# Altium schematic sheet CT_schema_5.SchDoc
size 300 x 247 mm
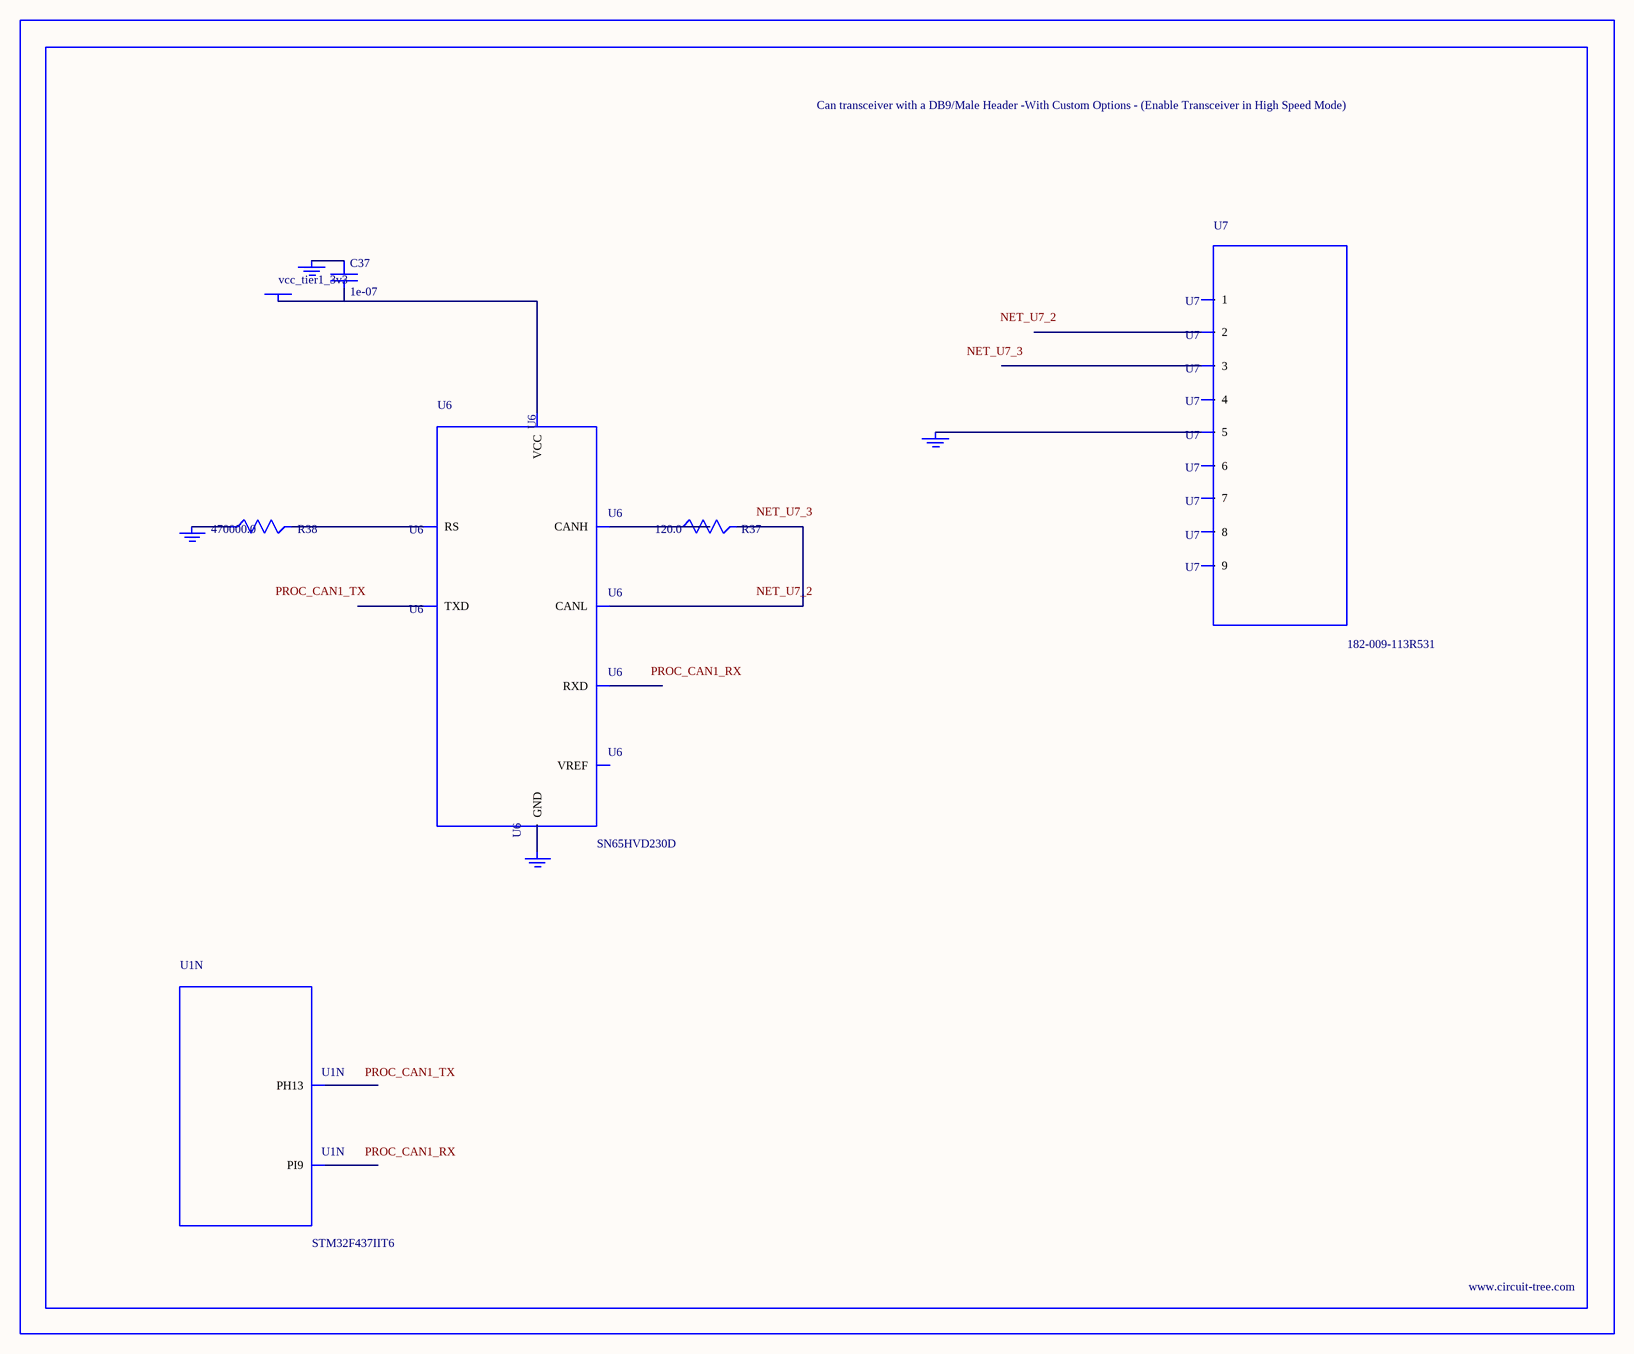
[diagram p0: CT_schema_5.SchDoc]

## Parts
BORDER4  (no value)
C37  1e-07  [C0402]
GND_INSTANCE_4_0  (no value)
GND_INSTANCE_4_1  (no value)
GND_INSTANCE_4_2  (no value)
GND_INSTANCE_4_3  (no value)
POWER_INSTANCE_4_0  vcc_tier1_3v3
R37  120.0  [R0603]
R38  470000.0  [R0603]
U1  STM32F437IIT6  [LQFP176]  (part N of 16)
U6  SN65HVD230D  [SOIC-8]
U7  182-009-113R531  [182-009-MALE]

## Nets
NetC37_1: C37.1 GND_INSTANCE_4_0.0(GND)
NetC37_2: C37.2 POWER_INSTANCE_4_0.0(PWR) U6.3(VCC)
NetGND_INSTANCE_4_1_0: GND_INSTANCE_4_1.0(GND) R38.1
NetGND_INSTANCE_4_2_0: GND_INSTANCE_4_2.0(GND) U6.2(GND)
NetGND_INSTANCE_4_3_0: GND_INSTANCE_4_3.0(GND) U7.5
NetR37_1: R37.1 U6.7(CANH)
NetR37_2: R37.2 U6.6(CANL)
NetR38_2: R38.2 U6.8(RS)

Not connected (* = marked no-connect by the designer): U1 11(PI9) 128(PH13); U6 1(TXD) 4(RXD) 5(VREF); U7 1 2 3 4 6 7 8 9

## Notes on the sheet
- Labels drawn without touching a wire or pin: NET_U7_2, NET_U7_3, PROC_CAN1_RX, PROC_CAN1_TX

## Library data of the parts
BORDER4 = BORDER_PAGE4
C37 = C0402C104K3RACTU
GND_INSTANCE_4_0-GND_INSTANCE_4_3 = GND
POWER_INSTANCE_4_0 = PWR
R37 = RC0603JR-07120RL
R38 = RC0603JR-07470KL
